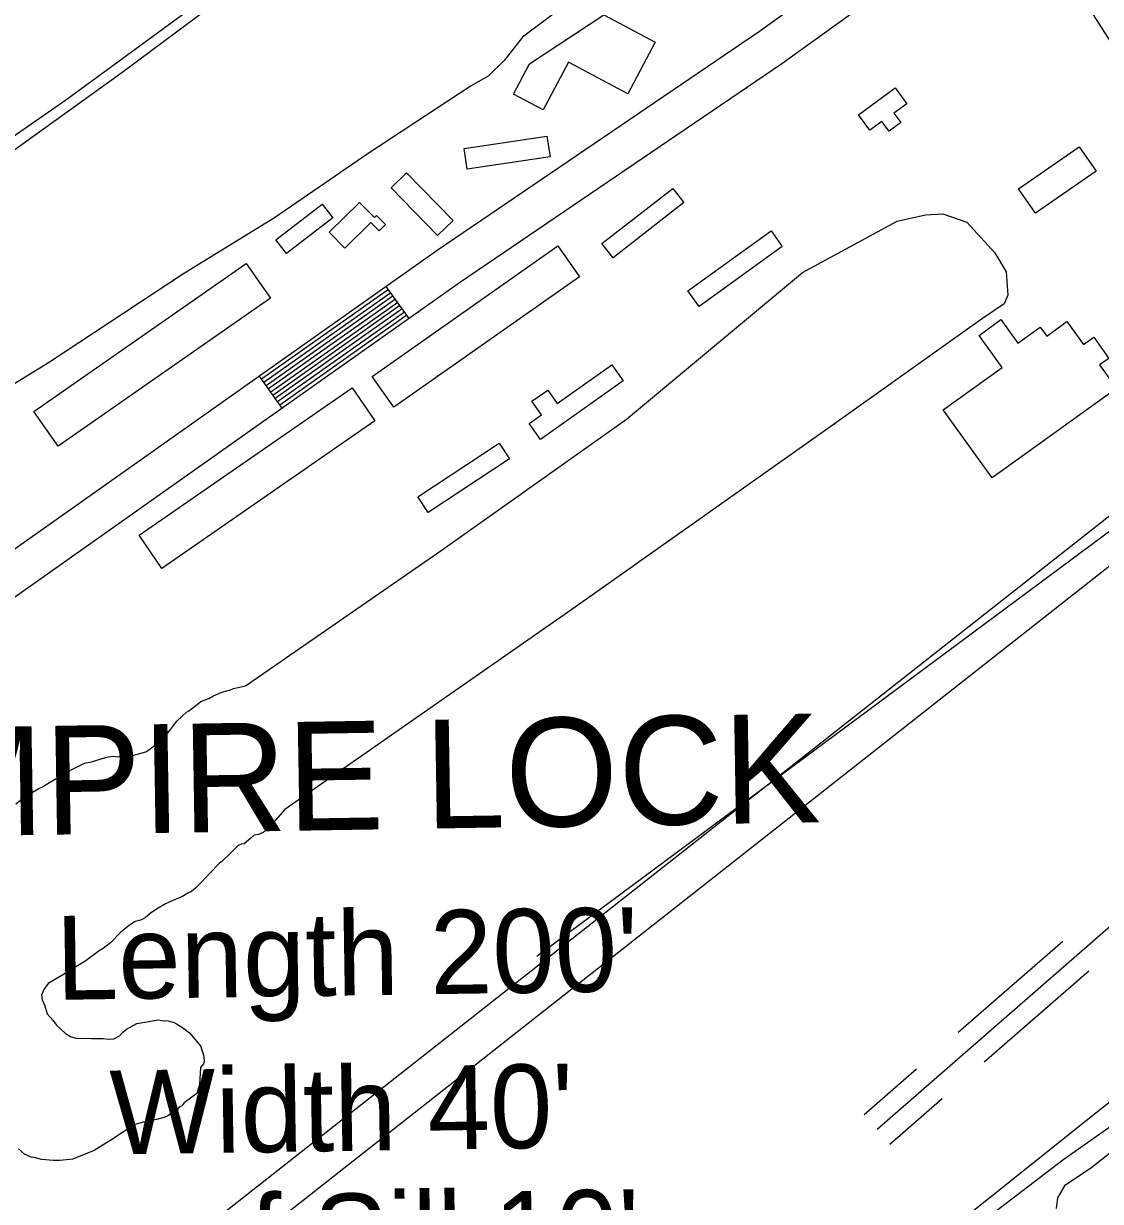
# Model space of a CAD drawing. Extents: x 3812694 to 3850888, y 319753 to 345638.
# Drawn here: x 3831459 to 3832281, y 327501 to 328399 of the extents above; entities that cross this region are included whole.
import ezdxf

# ---------------------------------------------------------------- set-up
doc = ezdxf.new("R2010")
doc.units = 0
for name, color, linetype in [('V-BLDG-OTLN', 7, 'Continuous'), ('V-BRDG-IDEN', 7, 'Continuous'), ('V-RIVR-IDEN', 7, 'Continuous'), ('V-ROAD-CNTR', 7, 'Continuous'), ('V-SITE-VEGE', 7, 'Continuous'), ('V-TOPO-SHOR', 7, 'Continuous')]:
    doc.layers.add(name, color=color, linetype=linetype)

msp = doc.modelspace()

# ---------------------------------------------------------------- linework, layer by layer
at = {"layer": 'V-BLDG-OTLN'}
for points in [[(3831940.93, 328385.17), (3831920.01, 328345.8), (3831874.7, 328369.88), (3831855.37, 328333.49), (3831832.67, 328345.56), (3831844.94, 328368.65), (3831901.61, 328406.07)], [(3832132.82, 328338.23), (3832123.02, 328331.01), (3832128.27, 328323.88), (3832119.33, 328317.29), (3832113.83, 328324.75), (3832104.72, 328318.04), (3832096.07, 328329.78), (3832123.93, 328350.3)], [(3831795.12, 328304.11), (3831858.28, 328313.5), (3831860.64, 328297.58), (3831797.48, 328288.2)], [(3832277.31, 328286.82), (3832231, 328254.68), (3832218.08, 328273.3), (3832264.38, 328305.44)], [(3831751.03, 328285.44), (3831786.62, 328249.06), (3831774.9, 328237.59), (3831739.31, 328273.98)], [(3831962.82, 328262.84), (3831908.71, 328220.73), (3831900.29, 328231.56), (3831954.4, 328273.66)], [(3831694.86, 328251.22), (3831659.57, 328223.95), (3831651.51, 328234.38), (3831686.8, 328261.65)], [(3831692.21, 328240.12), (3831715.29, 328262.91), (3831726.66, 328251.4), (3831728.26, 328252.98), (3831735.21, 328245.94), (3831730.34, 328241.14), (3831723.89, 328247.66), (3831704.08, 328228.1)], [(3832037.92, 328229.25), (3831974.36, 328183.48), (3831965.77, 328195.41), (3832029.33, 328241.17)], [(3831883.17, 328206.22), (3831741.51, 328106.61), (3831724.98, 328130.12), (3831866.64, 328229.72)], [(3831647.29, 328189.81), (3831485.21, 328076.94), (3831466.74, 328103.46), (3831628.82, 328216.34)], [(3832292.95, 328120.91), (3832198.01, 328052.66), (3832160.71, 328104.54), (3832205.7, 328136.88), (3832188.02, 328161.48), (3832204.67, 328173.45), (3832217.58, 328155.48), (3832234.76, 328167.83), (3832239.73, 328160.91), (3832255.12, 328171.98), (3832267.75, 328154.42), (3832275.53, 328160.01), (3832287.09, 328143.94), (3832280.04, 328138.88)], [(3831916.46, 328126.7), (3831853.29, 328082.13), (3831844.73, 328094.25), (3831854.03, 328100.81), (3831846.75, 328111.13), (3831858.98, 328119.77), (3831866.17, 328109.58), (3831907.81, 328138.96)], [(3831727, 328096.17), (3831564.52, 327983.69), (3831547.08, 328008.88), (3831709.56, 328121.36)], [(3831829.72, 328067.24), (3831767.69, 328026.23), (3831759.71, 328038.31), (3831821.73, 328079.32)]]:
    msp.add_lwpolyline(points, close=True, dxfattribs=at)
at = {"layer": 'V-ROAD-CNTR'}
for p, q in [((3831753.05, 328174.36), (3831735.73, 328198.86)), ((3831656.18, 328105.88), (3831638.86, 328130.38))]:
    msp.add_line(p, q, dxfattribs=at)
for points in [[(3832638.6, 327854.31), (3832295.88, 328374.05), (3831971.68, 328878.43), (3831841.95, 329078.43)], [(3832199.62, 328522.34), (3832020.39, 328393.27), (3831774.6, 328226.33), (3831290.67, 327884.27), (3831150.47, 327803.08)], [(3832216.51, 328497.53), (3832037.58, 328368.69), (3831791.69, 328201.67), (3831306.87, 327858.99), (3831162.85, 327775.58)], [(3831737.47, 328196.41), (3831640.59, 328127.93)], [(3831739.2, 328193.96), (3831642.32, 328125.48)], [(3831740.93, 328191.51), (3831644.05, 328123.03)], [(3831742.66, 328189.06), (3831645.79, 328120.58)], [(3831744.39, 328186.61), (3831647.52, 328118.13)], [(3831746.12, 328184.16), (3831649.25, 328115.68)], [(3831747.85, 328181.71), (3831650.98, 328113.23)], [(3831749.59, 328179.26), (3831652.71, 328110.78)], [(3831751.32, 328176.81), (3831654.44, 328108.33)], [(3832444.27, 328146.74), (3831373.33, 327304.5)], [(3832453.54, 328134.95), (3831850.52, 327687.43)], [(3832462.82, 328123.16), (3831385.93, 327276.24)], [(3832567.12, 327962.71), (3832478.63, 327889.94), (3832423.05, 327842.28), (3832333.83, 327750.34), (3832110.21, 327555.44)], [(3832252.1, 327699), (3832172.23, 327629.39)], [(3832271.81, 327676.38), (3832191.95, 327606.78)], [(3832140.29, 327601.55), (3832100.36, 327566.75)], [(3832160, 327578.93), (3832120.07, 327544.13)]]:
    msp.add_lwpolyline(points, dxfattribs=at)
at = {"layer": 'V-SITE-VEGE'}
for points in [[(3831335.21, 328219.3), (3831533.96, 328362.09), (3831715.66, 328497.6)], [(3831925.9, 328453.8), (3831839.74, 328389.05), (3831825.75, 328371.17), (3831813.48, 328359.22), (3831800.55, 328351.99), (3831721.94, 328300.32), (3831650.39, 328251.09), (3831581.71, 328208.98), (3831477.87, 328140.49), (3831414, 328101.33)], [(3831538.43, 327840.39), (3831542.11, 327840.89), (3831552.22, 327843.76), (3831554.51, 327845.17), (3831561.36, 327850.32), (3831563.65, 327852.18), (3831569.12, 327858.24), (3831571.39, 327861.03), (3831575.93, 327867.07), (3831580.04, 327870.8), (3831583.23, 327874.06), (3831585.06, 327875), (3831590.09, 327878.74), (3831594.21, 327882.02), (3831597.42, 327883.43), (3831600.17, 327884.39), (3831603.38, 327886.26), (3831610.26, 327889.1), (3831613.02, 327890.06), (3831616.7, 327891.02), (3831618.99, 327891.97), (3831621.29, 327892.45), (3831628.27, 327893.96), (3831778.41, 327997.81), (3831919.13, 328097.42), (3832053.23, 328209.38), (3832125.48, 328248.57), (3832147.29, 328253.54), (3832160.28, 328254.27), (3832178.66, 328247.97), (3832200.19, 328224.57), (3832208.62, 328209.89), (3832210, 328192.18), (3832207.11, 328185.65), (3832190.69, 328174.24), (3832069.91, 328088.43), (3831879.92, 327954.01), (3831658.25, 327799.74)], [(3831453.09, 327803.96), (3831460.86, 327810.04), (3831470.48, 327815.68), (3831472.77, 327816.62), (3831478.72, 327820.38), (3831488.8, 327826.48), (3831495.67, 327830.24), (3831505.3, 327834.96), (3831510.82, 327835.94), (3831521.38, 327839.28), (3831523.68, 327839.76), (3831526.9, 327840.26), (3831531.52, 327839.85), (3831538.43, 327840.39)], [(3831658.25, 327799.74), (3831647.32, 327787.18), (3831641.85, 327782.05), (3831638.18, 327780.62), (3831634.96, 327780.13), (3831632.22, 327777.8), (3831627.19, 327773.59), (3831624.89, 327773.11), (3831622.6, 327772.16), (3831617.13, 327766.57), (3831610.28, 327760.04), (3831608.46, 327758.64), (3831601.16, 327751.18), (3831594.78, 327744.2), (3831590.23, 327739.54), (3831587.02, 327737.2), (3831584.27, 327735.79), (3831579.7, 327732.97), (3831574.64, 327731.08), (3831567.31, 327727.77), (3831560.44, 327723.55), (3831555.4, 327720.26), (3831551.75, 327717), (3831548.09, 327715.12), (3831543.95, 327714.15), (3831539.83, 327711.34), (3831532.98, 327705.73), (3831525.23, 327697.81), (3831522.02, 327695.48), (3831519.74, 327693.6), (3831516.53, 327691.73), (3831505.56, 327683.77), (3831498.69, 327679.55), (3831493.66, 327676.27), (3831477.62, 327666.87), (3831474.45, 327662.23), (3831472.65, 327658.06), (3831473.15, 327654.38), (3831475.05, 327649.79), (3831476.96, 327643.82), (3831481.16, 327638.79), (3831483.96, 327635.14), (3831490.95, 327628.76), (3831494.66, 327626.5), (3831498.82, 327625.16), (3831510.81, 327624.83), (3831520.03, 327624.93), (3831523.72, 327624.51), (3831527.87, 327624.55), (3831531.99, 327626.9), (3831534.73, 327629.7), (3831537.46, 327632.03), (3831545.25, 327636.27), (3831561.82, 327639.21), (3831564.13, 327638.78), (3831569.2, 327638.37), (3831573.82, 327637.04), (3831575.68, 327636.14), (3831581.25, 327632.51), (3831585.43, 327629.33), (3831592.44, 327621.11), (3831593.84, 327619.28), (3831596.22, 327612.39), (3831596.72, 327608.24), (3831596.29, 327605.47), (3831594.02, 327602.69), (3831593.24, 327589.77), (3831591.01, 327582.83), (3831581.41, 327575.82), (3831579.59, 327573.49), (3831577.75, 327572.55), (3831575.93, 327570.22), (3831569.07, 327566), (3831566.31, 327564.59), (3831560.34, 327563.14), (3831550.22, 327561.19), (3831540.57, 327558.32), (3831538.74, 327556.91), (3831536.92, 327555.05), (3831525.94, 327547.55), (3831522.28, 327545.21), (3831512.66, 327539.57), (3831507.15, 327537.21), (3831496.14, 327532.94), (3831493.84, 327532.46), (3831486.47, 327531.91), (3831481.4, 327531.86), (3831475.86, 327532.26), (3831472.63, 327532.69), (3831467.08, 327534.01), (3831464.77, 327534.44), (3831459.68, 327536.69), (3831455.03, 327540.79)], [(3832126.64, 327436.51), (3832252.07, 327532.34), (3832324.66, 327583.41), (3832327.19, 327583.44), (3832330.3, 327577.89), (3832331.89, 327572.32), (3832273.98, 327526.49), (3832253.3, 327512.55), (3832247.82, 327503.35), (3832246.89, 327495.21)]]:
    msp.add_lwpolyline(points, dxfattribs=at)
at = {"layer": 'V-TOPO-SHOR'}
for points in [[(3832015.32, 328717.54), (3831908.7, 328643.7), (3831775.31, 328547.04), (3831632.34, 328444.5), (3831491.94, 328341.34), (3831345.74, 328240.04), (3831171.43, 328121.07), (3831071.76, 328058.24)], [(3832611.71, 327822.08), (3832542.96, 327773.31), (3832452.77, 327704.62), (3832368.05, 327639.92), (3832269.7, 327562.09), (3832157.3, 327472.3), (3832048.35, 327391.99), (3831944.89, 327312.13), (3831853.95, 327240.68), (3831752.88, 327158.88), (3831657.23, 327086.19), (3831564.71, 327014.72), (3831482.3, 326954.38), (3831387.84, 326880.53), (3831316.82, 326823.07)]]:
    msp.add_lwpolyline(points, dxfattribs=at)

# ---------------------------------------------------------------- texts
at = {"layer": 'V-BRDG-IDEN'}
for s, height, p in [("Length 200'", 63.9999, (3831483.97, 327654.37)), ("Width 40'", 64, (3831525.14, 327536.41)), ("Elev. of Sill 10'", 63.9999, (3831371.04, 327437.45))]:
    msp.add_text(s, height=height, rotation=0.86669, dxfattribs=at).set_placement(p)
at = {"layer": 'V-RIVR-IDEN'}
msp.add_text('EMPIRE LOCK', height=82.9998, rotation=0.92733, dxfattribs=at).set_placement((3831308.93, 327777.66))

doc.saveas('drawing.dxf')
